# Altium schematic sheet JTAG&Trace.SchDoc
size A4; Revision: C.2
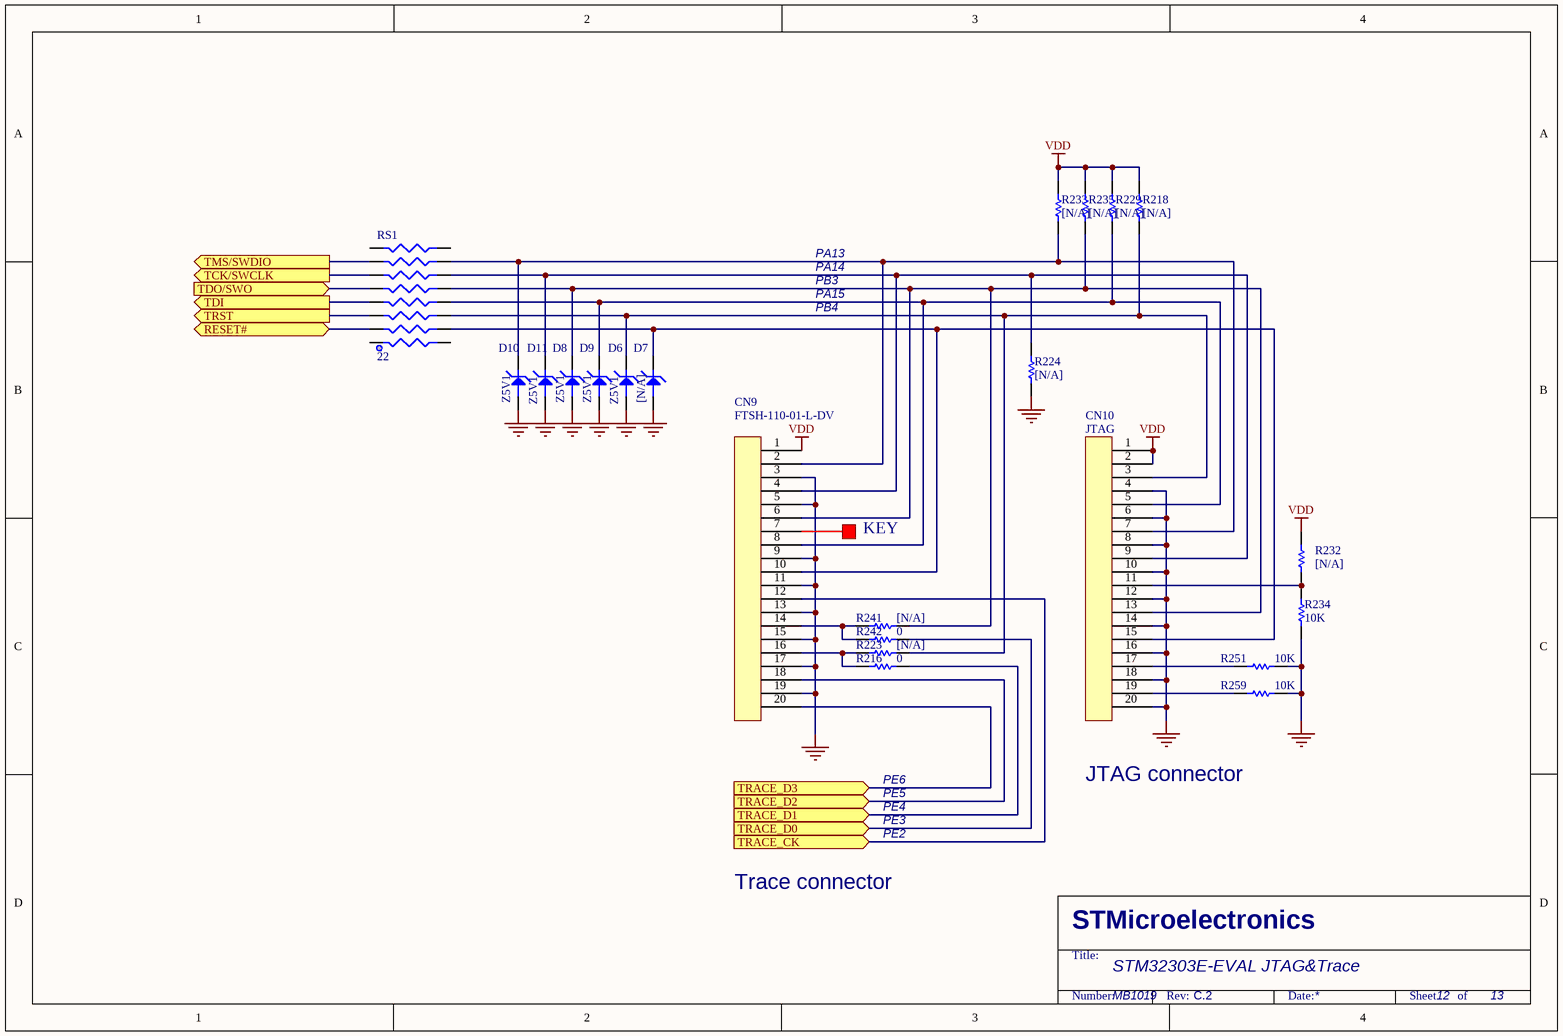
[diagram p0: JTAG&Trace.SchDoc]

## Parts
CN9  FTSH-110-01-L-DV  [FTSH-110-01-L-DV]
CN10  JTAG  [IDC20S]
D6  Z5V1  [SOT-23]
D7  [N/A]  [SOT-23]
D8  Z5V1  [SOT-23]
D9  Z5V1  [SOT-23]
D10  Z5V1  [SOT-23]
D11  Z5V1  [SOT-23]
R216  0  [0603R]
R218  [N/A]  [0603R]
R223  [N/A]  [0603R]
R224  [N/A]  [0603R]
R229  [N/A]  [0603R]
R232  [N/A]  [0603R]
R233  [N/A]  [0603R]
R234  10K  [0603R]
R235  [N/A]  [0603R]
R241  [N/A]  [0603R]
R242  0  [0603R]
R251  10K  [0603R]
R259  10K  [0603R]
RS1  22  [RES8B_0402]

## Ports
RESET# (bidir), TCK/SWCLK (out), TDI (out), TDO/SWO (in), TMS/SWDIO (out), TRACE_CK (in), TRACE_D0 (in), TRACE_D1 (in), TRACE_D2 (in), TRACE_D3 (in), TRST (out)

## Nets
GND: CN9.3 CN9.5 CN9.9 CN9.11 CN9.13 CN9.15 CN9.17 CN9.19 CN10.4 CN10.6 CN10.8 CN10.10 CN10.12 CN10.14 CN10.16 CN10.18 CN10.20 D6.2 D7.2 D8.2 D9.2 D10.2 D11.2 R224.1 R234.1 R251.1 R259.1
VDD: CN9.1 CN10.1 CN10.2 R218.2 R229.2 R232.2 R233.2 R235.2
RESET#: RS1.3 ; port RESET#
TCK/SWCLK: RS1.11 ; port TCK/SWCLK
TDI: RS1.7 ; port TDI
TDO/SWO: RS1.9 ; port TDO/SWO
TMS/SWDIO: RS1.13 ; port TMS/SWDIO
TRACE_CK: CN9.12 ; port TRACE_CK
TRACE_D0: R242.2 ; port TRACE_D0
TRACE_D1: R216.2 ; port TRACE_D1
TRACE_D2: CN9.18 ; port TRACE_D2
TRACE_D3: CN9.20 ; port TRACE_D3
TRST: RS1.5 ; port TRST
NetCN9_2: CN9.2 CN10.7 D10.3 R233.1 RS1.14
NetCN9_4: CN9.4 CN10.9 D11.3 R224.2 RS1.12
NetCN9_6: CN9.6 CN10.13 D8.3 R235.1 R241.2 RS1.10
NetCN9_8: CN9.8 CN10.5 D9.3 R229.1 RS1.8
NetCN9_10: CN9.10 CN10.15 D7.3 RS1.4
NetCN9_14: CN9.14 R241.1 R242.1
NetCN9_16: CN9.16 R216.1 R223.1
NetCN10_3: CN10.3 D6.3 R218.1 R223.2 RS1.6
NetCN10_11: CN10.11 R232.1 R234.2
NetCN10_17: CN10.17 R251.2
NetCN10_19: CN10.19 R259.2

Not connected (* = marked no-connect by the designer): CN9 7; RS1 1 2 15 16

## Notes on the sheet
- PA13
- PA14
- PB3
- PA15
- PB4
- KEY
- PE6
- JTAG connector
- PE5
- PE4
- PE3
- PE2
- Trace connector
- STM32303E-EVAL JTAG&Trace
- MB1019
- 12
- 13

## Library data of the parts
CN9 CN10 = 20PIN1
D6-D11 = BATS5V6
R216 R218 R223 R224 R229 R232-R235 R241 R242 R251 R259 = Res1: Resistor; Value: 1K
RS1 = RES8B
